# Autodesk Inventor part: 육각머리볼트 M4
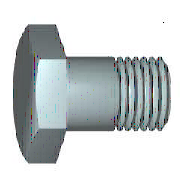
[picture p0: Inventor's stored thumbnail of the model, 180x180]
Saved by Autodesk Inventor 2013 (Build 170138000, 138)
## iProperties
IsCustomPart: 1
Created: 2012-02
Part Number: 육각머리볼트 M4
Material: 강철, 연강
Description: 6각 머리 볼트 및 6각 머리 나사
Document SubType Name: Modeling
Standard: KS B 1002
Designer: mduedu
Standards Organization: KS
Language: ko-KR
Size Designation: A + B M4 x 16
Categories: <MemberInstance><Categories><Category DisplayName="조임쇠" InternalName="e4da775c-781d-43d5-af7c-5136215cf5a6" Mnemonic="FSTN"><Category DisplayName="볼트" InternalN
Density: 1 g/cm^3
Author: mduedu
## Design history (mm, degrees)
sketch "스케치1"
  geometry: L1 (0, 2.94)-(0, 2); L2 (2.1, 2)-(16, 2); L3 (16, 2)-(16, 0); L4 (16, 0)-(-0.4, 0); L5 (-3.68, 0)-(19.28, 0) reference; L6 (-0.4, 0)-(-0.4, 2.94); L7 (-0.4, 2.94)-(0, 2.94); L8 (2.1, 2)-(1.67, 2); L9 (1.67, 2)-(0, 2); L10 (0, -0.588)-(0, 3.528) reference
  constraints: 16 end point, 2 collinear, 2 perpendicular, 1 parallel
  dimensions: "d0" = 16 distance between parallel lines of L3 L1 (= NLG); "d1" = 13.9 distance from line of L2.start L3 (= GEL); "d2" = 4 diameter of L2 L4 (= GD); "d9" = 0.4001 distance between parallel lines of L6 L1 (computed from SD); "d10" = 5.88 diameter of L7 L4 (= SD2); "d13" = 0.42952 distance of L2.start L8.end (computed from GAL); "d14" = 4 diameter of L9 L4 (= BDM)
revolve "본체" sketch "스케치1" stored, may be unused: angle "d12" = 90 deg
sketch "스케치2"
  geometry: L1 (0, 4.041)-(3.5, 2.021); L2 (3.5, 2.021)-(3.5, -2.021); L3 (3.5, -2.021)-(0, -4.041); L4 (0, -4.041)-(-3.5, -2.021); L5 (-3.5, -2.021)-(-3.5, 2.021); L6 (-3.5, 2.021)-(0, 4.041); 2 further points
  constraints: 12 end point, 1 coincident, 1 vertical, 11 other
  dimensions: "d11" = 7 distance between parallel lines of L5 L2 (= SW)
extrude "머리" join sketch "스케치2" distance "d3" = 2.4 (= KOH - SD); taper "d4" = 0 deg
sketch "스케치4"
  geometry: L1 (-2.8, 3.5)-(-2.8, 4.041); L2 (-2.8, 4.041)-(-2.487, 4.041); L3 (-2.487, 4.041)-(-2.8, 3.5); L4 (-3.28, 0)-(0.08, 0) reference; L5 (-0.4, 4.041)-(-2.8, 4.041) reference; L6 (-2.8, 2.021)-(-2.8, 4.041) reference
  constraints: 6 end point, 2 collinear, 1 perpendicular, 1 vertical
  dimensions: "d5" = 30 deg angle of L3 L1 (= ANG1); "d19" = 7 diameter of L1.start L4 (= SW0)
revolve "모따기1" sketch "스케치4" stored, may be unused: angle "d21" = 90 deg
workplane "Work Plane1"
body "Solid1"
feature "스레드" dims "d15" = 13.9 (= GEL), "d16" = 0
chamfer "모따기2" distance "d6" = 0.42941 (= -0.5 x SPD + 0.5 x GD); stored, may be unused: second distance "d7" = 0.42952 (computed from GUL), angle "d55" = 45 deg
other parameters: "NLG" = 16 [user parameter; used in 1 equation term], "GD" = 4 (= NND) [user parameter; used in 2 equation terms], "BDM" = 4 (= NND) [user parameter; used in 1 equation term], "KOH" = 2.8 [user parameter; used in 1 equation term], "GEL" = 13.9 [user parameter; used in 2 equation terms], "SW" = 7 [user parameter; used in 3 equation terms], "SW0" = 7 (= SW) [user parameter; used in 1 equation term], "SPD" = 3.14117 (= NND - 1.2269 x PTC) [user parameter; used in 1 equation term], "SD2" = 5.88 (= SDH) [user parameter; used in 1 equation term], "SD" = 0.4 [user parameter; used in 2 equation terms], "ANG1" = 30 deg [user parameter; used in 1 equation term], "GAL" = 0.42941 (= 0.61345 x PTC) [user parameter; used in 1 equation term], "GUL" = 0.42941 (= 0.61345 x PTC) [user parameter; used in 1 equation term], "d8" = 0, "RR" = 0.2 [user parameter], "d57" = 0, "d58" = 0, "TPU" = 14.28571 (computed from PTC) [user parameter], "GD1" = 3.14117 (= THREADDIA - 1.2269 x PTC) [user parameter], "THREADDIA" = 4 [user parameter; used in 1 equation term], "SDH" = 5.88 [user parameter; used in 1 equation term], "SDHG" = 2.1 [user parameter], "TOA" = 30 deg [user parameter], "PTC" = 0.7 [user parameter; used in 5 equation terms], "NND" = 4 [user parameter; used in 3 equation terms], "E0" = 8.085 (= 1.155 x SW) [user parameter]
